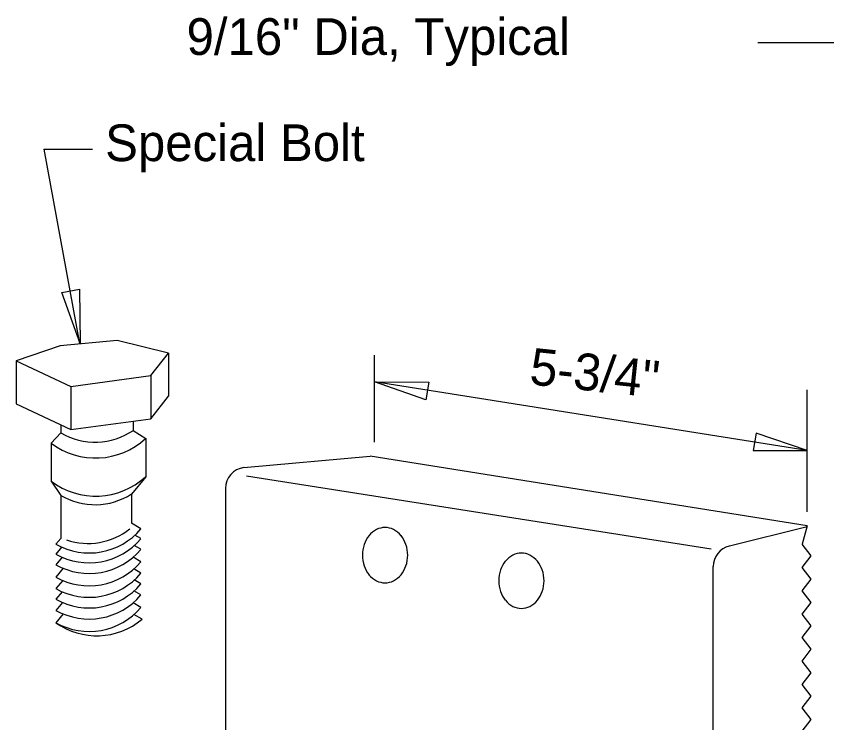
# Model space of a CAD drawing. Extents: x 12.3 to 19.6, y 5.9 to 16.2.
# Drawn here: x 16.163 to 17.486, y 9.704 to 10.857 of the extents above; entities that cross this region are included whole.
import ezdxf

# ---------------------------------------------------------------- set-up
doc = ezdxf.new("R2010")
doc.units = 0
for name, color, linetype in [('DETL-DIMS', 7, 'Continuous'), ('DETL-LINE', 7, 'Continuous'), ('DETL-NOTE', 7, 'Continuous')]:
    doc.layers.add(name, color=color, linetype=linetype)

msp = doc.modelspace()

# ---------------------------------------------------------------- linework, layer by layer
at = {"layer": 'DETL-DIMS'}
for p, q in [((17.61, 10.8139), (17.3733, 10.8139)), ((16.208, 10.6406), (16.2661, 10.3233)), ((16.208, 10.6406), (16.2872, 10.6406)), ((16.7478, 10.1618), (16.7478, 10.3042)), ((17.4541, 10.1481), (16.7478, 10.2607)), ((17.4541, 10.0483), (17.4541, 10.2472))]:
    msp.add_line(p, q, dxfattribs=at)
for points in [[(16.8362, 10.2599), (16.8313, 10.2312), (16.7478, 10.2604)], [(17.3704, 10.1768), (17.3656, 10.1481), (17.4541, 10.1481)]]:
    msp.add_lwpolyline(points, close=True, dxfattribs=at)
at = {"layer": 'DETL-LINE'}
for p, q in [((16.3278, 10.3278), (16.2347, 10.3192)), ((16.4115, 10.3075), (16.3278, 10.3278)), ((16.2347, 10.3192), (16.1628, 10.2949)), ((16.3826, 10.2707), (16.4115, 10.3075)), ((16.4115, 10.3075), (16.4115, 10.2371)), ((16.1628, 10.2949), (16.1628, 10.2246)), ((16.1628, 10.2949), (16.2519, 10.2527)), ((16.2519, 10.2527), (16.3826, 10.2707)), ((16.3826, 10.2707), (16.3826, 10.2003)), ((16.2519, 10.2527), (16.2519, 10.1824)), ((16.3826, 10.2003), (16.4115, 10.2371)), ((16.1628, 10.2246), (16.2519, 10.1824)), ((16.2355, 10.1902), (16.2355, 10.177)), ((16.2519, 10.1824), (16.3826, 10.2003)), ((16.3539, 10.1964), (16.3539, 10.1812)), ((16.2355, 10.177), (16.2196, 10.1605)), ((16.3539, 10.1812), (16.3741, 10.1678)), ((16.3741, 10.1678), (16.3741, 10.1056)), ((16.2196, 10.1605), (16.2196, 10.0982)), ((16.5345, 10.1206), (16.7407, 10.1393)), ((17.4541, 10.0256), (16.7407, 10.1393)), ((16.2196, 10.0982), (16.2355, 10.075)), ((16.3741, 10.1056), (16.351, 10.0773)), ((17.2973, 9.9871), (16.5386, 10.1062)), ((16.5043, 10.0862), (16.5043, 9.6712)), ((16.2355, 10.075), (16.2355, 10.0049)), ((16.351, 10.0773), (16.351, 10.0295)), ((16.3661, 10.0204), (16.351, 10.0295)), ((17.4536, 10.0237), (17.3268, 9.9924)), ((17.4541, 10.0256), (17.4456, 9.9955)), ((16.2355, 10.0049), (16.2274, 9.9953)), ((16.3661, 10.0044), (16.3564, 10.0102)), ((16.2369, 9.9906), (16.2274, 9.9793)), ((16.3661, 9.987), (16.3555, 9.9934)), ((17.4606, 9.9764), (17.4456, 9.9955)), ((17.4456, 9.9573), (17.4606, 9.9764)), ((16.2378, 9.9742), (16.2274, 9.9619)), ((16.3661, 9.9668), (16.3536, 9.9743)), ((16.2395, 9.956), (16.2274, 9.9417)), ((16.3661, 9.948), (16.3545, 9.9549)), ((17.3004, 9.4304), (17.3004, 9.9587)), ((17.4606, 9.9382), (17.4456, 9.9573)), ((16.3661, 9.9305), (16.3555, 9.9369)), ((17.4456, 9.9191), (17.4606, 9.9382)), ((16.2386, 9.9362), (16.2274, 9.9229)), ((16.2378, 9.9177), (16.2274, 9.9055)), ((16.3661, 9.9124), (16.355, 9.9191)), ((17.4606, 9.9001), (17.4456, 9.9191)), ((16.2382, 9.9001), (16.2274, 9.8873)), ((16.3661, 9.8922), (16.3536, 9.8997)), ((17.4456, 9.881), (17.4606, 9.9001)), ((16.2395, 9.8815), (16.2274, 9.8671)), ((16.3682, 9.8727), (16.3549, 9.8807)), ((17.4606, 9.8619), (17.4456, 9.881)), ((17.4456, 9.8428), (17.4606, 9.8619)), ((17.4606, 9.8237), (17.4456, 9.8428)), ((17.4456, 9.8046), (17.4606, 9.8237)), ((17.4606, 9.7855), (17.4456, 9.8046)), ((17.4456, 9.7664), (17.4606, 9.7855)), ((17.4606, 9.7474), (17.4456, 9.7664)), ((17.4456, 9.7283), (17.4606, 9.7474)), ((17.4606, 9.7092), (17.4456, 9.7283)), ((17.4456, 9.6901), (17.4606, 9.7092))]:
    msp.add_line(p, q, dxfattribs=at)
msp.add_lwpolyline([(16.2374, 10.4065), (16.266, 10.4116), (16.2669, 10.3231)], close=True, dxfattribs=at)
for centre, radius, start, end in [((16.2914, 10.2716), 0.1099, 239.4268, 304.7035), ((16.2924, 10.257), 0.1209, 232.945, 312.4826), ((16.539, 10.0862), 0.0347, 97.5272, 180), ((16.2924, 10.1947), 0.1209, 232.945, 312.4826), ((16.2914, 10.1697), 0.1099, 239.4268, 302.8559), ((16.2817, 10.0915), 0.1105, 240.5948, 319.9009), ((16.28, 10.1052), 0.1087, 251.153, 308.7624), ((16.7683, 9.9849), 0.0384, 116.7848, 140.6296), ((16.7648, 9.992), 0.0306, 90, 116.7848), ((16.7648, 9.992), 0.0306, 63.2152, 90), ((16.7613, 9.9849), 0.0384, 39.3704, 63.2152), ((16.2817, 10.0755), 0.1105, 240.5948, 319.9009), ((16.7739, 9.9804), 0.0456, 140.6296, 161.2281), ((16.7557, 9.9804), 0.0456, 18.7719, 39.3704), ((16.7826, 9.9774), 0.0548, 161.2281, 180), ((16.747, 9.9774), 0.0548, 360, 18.7719), ((17.3351, 9.9587), 0.0347, 103.8779, 180), ((16.2817, 10.0581), 0.1105, 240.5948, 319.9009), ((16.7826, 9.9774), 0.0548, 180, 198.7719), ((16.747, 9.9774), 0.0548, 341.2281, 0), ((16.9909, 9.9431), 0.0384, 116.7848, 140.6296), ((16.9873, 9.9502), 0.0306, 90, 116.7848), ((16.9873, 9.9502), 0.0306, 63.2152, 90), ((16.9838, 9.9431), 0.0384, 39.3704, 63.2152), ((16.2817, 10.0379), 0.1105, 240.5948, 319.9009), ((16.9964, 9.9386), 0.0456, 140.6296, 161.2281), ((16.9782, 9.9386), 0.0456, 18.7719, 39.3704), ((16.7739, 9.9745), 0.0456, 198.7719, 219.3704), ((16.7557, 9.9745), 0.0456, 320.6296, 341.2281), ((17.0051, 9.9356), 0.0548, 161.2281, 180), ((16.9695, 9.9356), 0.0548, 0, 18.7719), ((16.2817, 10.0191), 0.1105, 240.5948, 319.9009), ((16.7683, 9.9699), 0.0384, 219.3704, 243.2152), ((16.7613, 9.9699), 0.0384, 296.7848, 320.6296), ((16.2817, 10.0017), 0.1105, 240.5948, 319.9009), ((16.7648, 9.9629), 0.0306, 243.2152, 270), ((16.7648, 9.9629), 0.0306, 270, 296.7848), ((17.0051, 9.9356), 0.0548, 180, 198.7719), ((16.9695, 9.9356), 0.0548, 341.2281, 360), ((16.2817, 9.9836), 0.1105, 240.5948, 319.9009), ((16.9964, 9.9327), 0.0456, 198.7719, 219.3704), ((16.9782, 9.9327), 0.0456, 320.6296, 341.2281), ((16.9909, 9.9281), 0.0384, 219.3704, 243.2152), ((16.9838, 9.9281), 0.0384, 296.7848, 320.6296), ((16.2817, 9.9634), 0.1105, 240.5948, 319.9009), ((16.9873, 9.9211), 0.0306, 243.2152, 270), ((16.9873, 9.9211), 0.0306, 270, 296.7848), ((16.2942, 9.9608), 0.115, 234.4998, 310.0333)]:
    msp.add_arc(centre, radius, start, end, dxfattribs=at)

# ---------------------------------------------------------------- texts
at = {"layer": 'DETL-NOTE'}
for s, p in [('9/16" Dia, Typical', (16.4408, 10.7942)), ('Special Bolt', (16.3079, 10.6208))]:
    msp.add_text(s, height=0.06, dxfattribs=at).set_placement(p)
msp.add_text('5-3/4"', height=0.06, rotation=353.9782, dxfattribs=at).set_placement((16.9991, 10.2565))

doc.saveas('drawing.dxf')
